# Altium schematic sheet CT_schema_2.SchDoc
size 328 x 327 mm
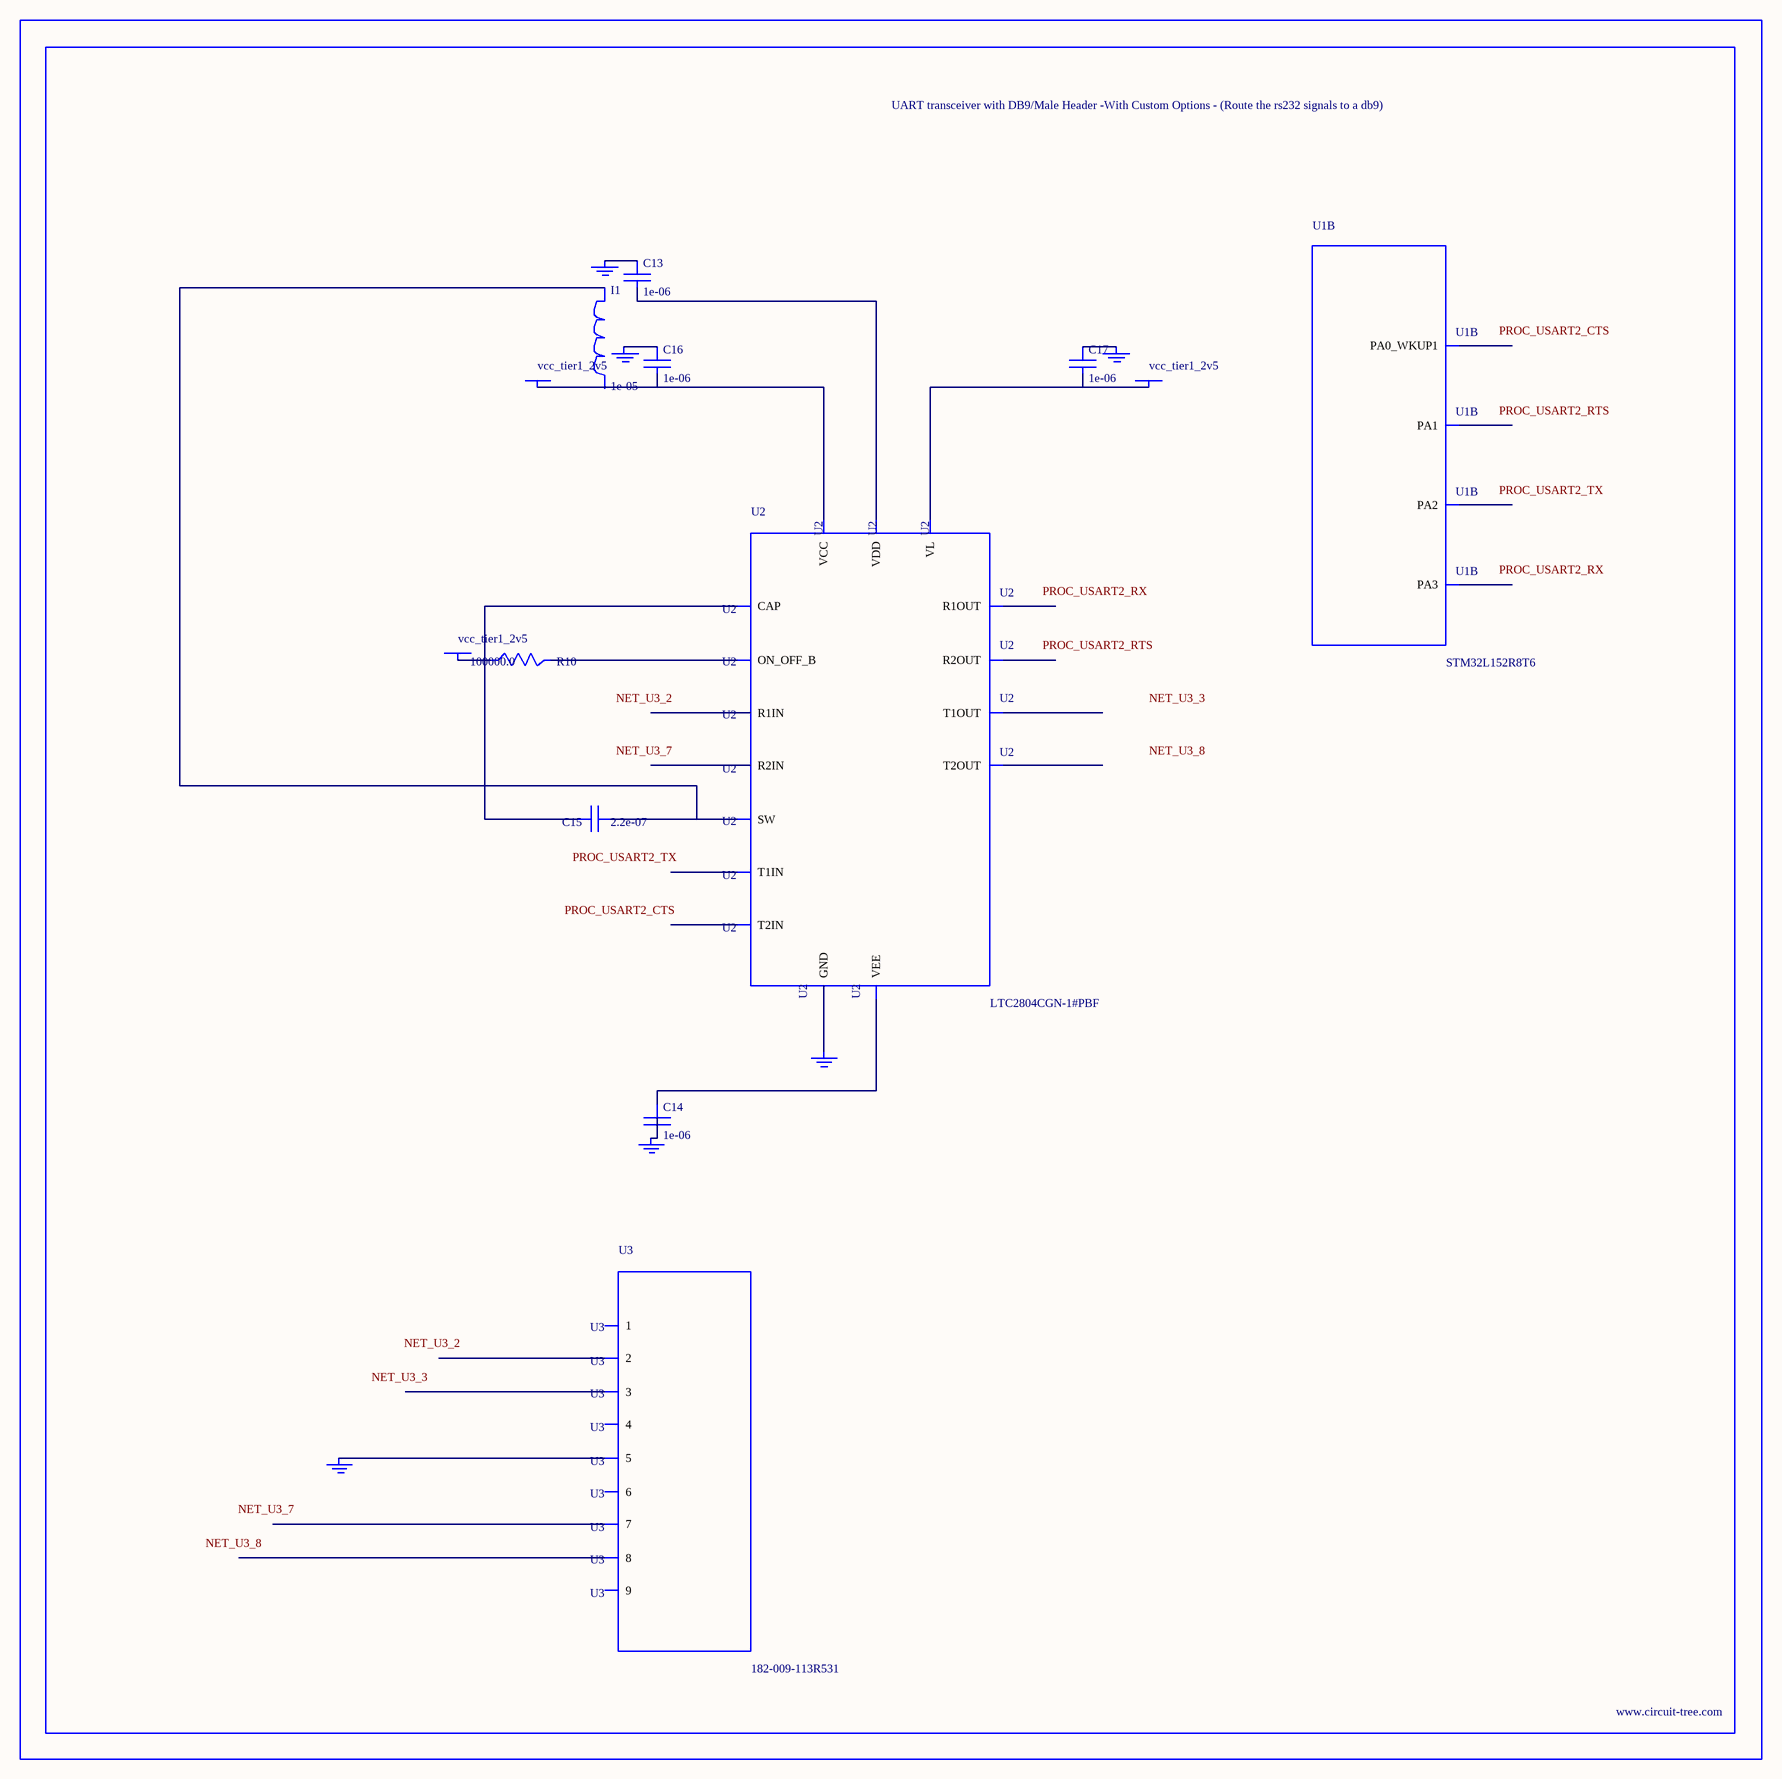
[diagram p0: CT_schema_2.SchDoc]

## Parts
BORDER1  (no value)
C13  1e-06  [C0603]
C14  1e-06  [C0603]
C15  2.2e-07  [C0603]
C16  1e-06  [C0603]
C17  1e-06  [C0603]
GND_INSTANCE_1_0  (no value)
GND_INSTANCE_1_1  (no value)
GND_INSTANCE_1_2  (no value)
GND_INSTANCE_1_3  (no value)
GND_INSTANCE_1_4  (no value)
GND_INSTANCE_1_5  (no value)
I1  1e-05  [L1210]
POWER_INSTANCE_1_0  vcc_tier1_2v5
POWER_INSTANCE_1_1  vcc_tier1_2v5
POWER_INSTANCE_1_2  vcc_tier1_2v5
R10  100000.0  [R0603]
U1  STM32L152R8T6  [LQFP64]  (part B of 6)
U2  LTC2804CGN-1#PBF  [SSOP-16]
U3  182-009-113R531  [182-009-MALE]

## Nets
NetC13_1: C13.1 GND_INSTANCE_1_1.0(GND)
NetC13_2: C13.2 U2.6(VDD)
NetC14_1: C14.1 U2.9(VEE)
NetC14_2: C14.2 GND_INSTANCE_1_2.0(GND)
NetC15_1: C15.1 I1.1 U2.7(SW)
NetC15_2: C15.2 U2.10(CAP)
NetC16_1: C16.1 GND_INSTANCE_1_0.0(GND)
NetC16_2: C16.2 POWER_INSTANCE_1_0.0(PWR) U2.5(VCC)
NetC17_1: C17.1 GND_INSTANCE_1_3.0(GND)
NetC17_2: C17.2 POWER_INSTANCE_1_2.0(PWR) U2.12(VL)
NetGND_INSTANCE_1_4_0: GND_INSTANCE_1_4.0(GND) U2.8(GND)
NetGND_INSTANCE_1_5_0: GND_INSTANCE_1_5.0(GND) U3.5
NetPOWER_INSTANCE_1_1_0: POWER_INSTANCE_1_1.0(PWR) R10.1
NetR10_2: R10.2 U2.11(ON_OFF_B)

Not connected (* = marked no-connect by the designer): I1 2; U1 14(PA0_WKUP1) 15(PA1) 16(PA2) 17(PA3); U2 1(R1IN) 2(R2IN) 3(T1OUT) 4(T2OUT) 13(T2IN) 14(T1IN) 15(R2OUT) 16(R1OUT); U3 1 2 3 4 6 7 8 9

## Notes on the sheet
- Labels drawn without touching a wire or pin: NET_U3_2, NET_U3_3, NET_U3_7, NET_U3_8, PROC_USART2_CTS, PROC_USART2_RTS, PROC_USART2_RX, PROC_USART2_TX

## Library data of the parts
BORDER1 = BORDER_PAGE1
C13 C14 C16 C17 = C0603C105K3RACTU
C15 = C0603C224K3RAC
GND_INSTANCE_1_0-GND_INSTANCE_1_5 = GND
I1 = CBC3225T100MR
POWER_INSTANCE_1_0-POWER_INSTANCE_1_2 = PWR
R10 = RC0603JR-07100KL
